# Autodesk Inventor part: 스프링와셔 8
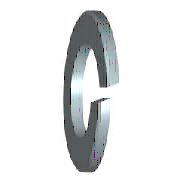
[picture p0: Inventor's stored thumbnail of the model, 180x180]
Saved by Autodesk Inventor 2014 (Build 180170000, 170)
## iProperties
IsCustomPart: 1
Created: 2012-02
Part Number: 스프링와셔 8
Material: 강철, 연강
Description: 스프링 잠금 와셔
Document SubType Name: Modeling
Standard: KS B 1324
Designer: mduedu
Standards Organization: KS
Language: ko-KR
Size Designation: 번호 3 - 8
Categories: <MemberInstance><Categories><Category DisplayName="조임쇠" InternalName="e4da775c-781d-43d5-af7c-5136215cf5a6" Mnemonic="FSTN"><Category DisplayName="와셔" InternalN
Density: 1 g/cm^3
Appearance: Blue - Wall Paint - Glossy
Author: mduedu
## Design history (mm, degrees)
sketch "스케치1"
  geometry: C1 r 7.4 at (0, 0); C2 r 4.1 at (0, 0); 1 further point
  constraints: 2 centre point, 2 coincident
  dimensions: "d0" = 8.2 diameter of C2 (= SD1); "d1" = 14.8 diameter of C1 (= SD2)
extrude "본체" new body sketch "스케치1" distance "d2" = 2.5 (= SD); taper "d3" = 0 deg
sketch "스케치2"
  geometry: L1 (0, -4.1)-(0, 4.1) reference; L2 (2.5, 7.4)-(2.5, -7.4) reference; L3 (-1.2, 0)-(7.2, 0) reference; L4 (0, -0.5)-(2.5, 0.41); L5 (0, 0.5)-(2.5, 1.41)
  constraints: 4 end point, 4 point on line, 1 parallel
  dimensions: "d4" = 0.5 distance from line of L3 L4.start (= 0.2 x SD); "d5" = 0.5 distance from line of L3 L5.start (= 0.2 x SD); "d6" = 70 deg angle of L2 L4 (= FAWI)
extrude "절단부" cut sketch "스케치2" stored distance "d7" = 2.5 (= SD); taper "d8" = 0 deg
workaxis "Work Axis1"
workplane "Work Plane1"
body "Solid1"
other parameters: "SD1" = 8.2 [user parameter; used in 1 equation term], "SD2" = 14.8 [user parameter; used in 1 equation term], "SD" = 2.5 [user parameter; used in 4 equation terms], "FAWI" = 70 deg [user parameter; used in 1 equation term], "d9" = 0, "d10" = 0, "d11" = 0, "d12" = 0, "SDI" = 3.3 [user parameter], "NND" = 8 [user parameter]
